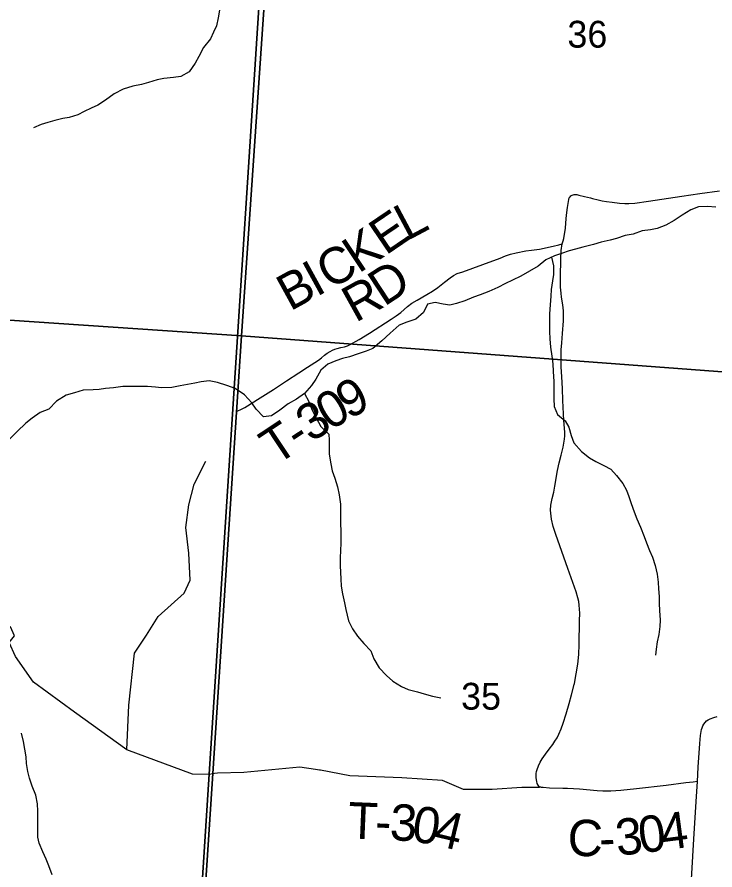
# Model space of a CAD drawing. Extents: x 0 to 34, y 0 to 22.
# Drawn here: x 3.095 to 4.184, y 17.112 to 18.443 of the extents above; entities that cross this region are included whole.
import ezdxf

# ---------------------------------------------------------------- set-up
doc = ezdxf.new("R2010")
doc.units = 0
for name, color, linetype in [('GM_X_Corporation', 7, 'Continuous'), ('GM_X_County_Road', 7, 'Continuous'), ('GM_X_County_Road_Text', 7, 'Continuous'), ('GM_X_Minor_River', 7, 'Continuous'), ('GM_X_Section_Text', 7, 'Continuous'), ('GM_X_Township_Road', 7, 'Continuous'), ('GM_X_Township_Road_Text', 7, 'Continuous'), ('GM_X_Township_Text', 7, 'Continuous')]:
    doc.layers.add(name, color=color, linetype=linetype)

msp = doc.modelspace()

# ---------------------------------------------------------------- linework, layer by layer
at = {"layer": 'GM_X_Corporation'}
for points in [[(2.1, 19.0816), (2.1, 14.1), (3.1902, 14.1), (3.1919, 14.1255), (3.2339, 14.7735), (3.2844, 15.554), (3.3059, 15.8844), (3.3516, 16.5898), (3.3951, 17.2616), (3.507, 18.9883), (2.9513, 19.0267), (2.509, 19.0572), (2.4972, 19.0545), (2.4649, 19.0567)], [(2.5061, 19.0541), (2.5182, 19.0533), (3.5166, 18.9866), (3.4457, 17.9455), (2.436, 18.0137)], [(3.5166, 18.9866), (4.5247, 18.9179), (4.4596, 17.8697), (3.4457, 17.9455)], [(2.436, 18.0137), (3.4457, 17.9455), (3.3779, 16.9127), (2.3682, 16.9741)], [(3.4457, 17.9455), (4.4596, 17.8697), (4.3853, 16.8539), (3.3779, 16.9127)]]:
    msp.add_lwpolyline(points, close=True, dxfattribs=at)
at = {"layer": 'GM_X_County_Road'}
for points in [[(4.1567, 17.2497), (4.1502, 17.249), (4.1386, 17.2477), (4.1078, 17.2439), (4.0617, 17.2384), (4.0371, 17.236), (4.0216, 17.235), (4.0093, 17.2348), (4.0001, 17.2352), (3.9725, 17.2378), (3.9539, 17.2388), (3.9469, 17.2391), (3.9261, 17.2398), (3.9159, 17.2405), (3.9136, 17.2406), (3.9122, 17.2409), (3.9105, 17.2416), (3.9093, 17.2427), (3.9081, 17.2442), (3.9069, 17.2468), (3.9059, 17.2502), (3.9056, 17.2523), (3.905, 17.2563), (3.905, 17.2594), (3.9052, 17.2625), (3.9057, 17.2655), (3.9065, 17.2685), (3.9086, 17.2743), (3.9112, 17.2799), (3.9144, 17.2851), (3.9198, 17.2927), (3.9254, 17.3002), (3.9309, 17.3076), (3.9344, 17.3128), (3.9376, 17.3181), (3.9404, 17.3236), (3.9441, 17.3322), (3.9473, 17.3409), (3.9519, 17.3558), (3.9566, 17.3716), (3.9603, 17.3852), (3.9644, 17.4013), (3.9647, 17.4027), (3.9677, 17.4182), (3.9701, 17.4329), (3.9715, 17.4483), (3.9722, 17.4637), (3.9728, 17.5007), (3.9731, 17.5129), (3.9729, 17.519), (3.9724, 17.525), (3.9714, 17.531), (3.97, 17.5369), (3.9676, 17.546), (3.9547, 17.5825), (3.9356, 17.6354), (3.9318, 17.6481), (3.9291, 17.6596), (3.9279, 17.6686), (3.9277, 17.6733), (3.9282, 17.6814), (3.9302, 17.6915), (3.9325, 17.7017), (3.9344, 17.7109), (3.9385, 17.7355), (3.9411, 17.7475), (3.9442, 17.7595), (3.947, 17.7717), (3.9482, 17.7781), (3.9491, 17.7842), (3.9496, 17.7895), (3.9496, 17.795), (3.9481, 17.8135), (3.9469, 17.8446), (3.9463, 17.8633), (3.9451, 17.8818), (3.9443, 17.8974), (3.9439, 17.9132), (3.9441, 17.9238), (3.9451, 17.9345), (3.9462, 17.9495), (3.9476, 17.9692), (3.9479, 17.9784), (3.9477, 17.9845), (3.9469, 17.9938), (3.9447, 18.006), (3.9439, 18.0121), (3.9433, 18.0215), (3.9431, 18.0371), (3.9435, 18.066), (3.9443, 18.0786), (3.9456, 18.0893), (3.9473, 18.094), (3.9482, 18.0978), (3.9488, 18.1011), (3.9507, 18.1131), (3.9514, 18.1219), (3.9524, 18.1341), (3.9539, 18.1462), (3.9553, 18.1554), (3.956, 18.1586), (3.9568, 18.1608), (3.9579, 18.1628), (3.9591, 18.164), (3.9602, 18.1649), (3.9615, 18.1654), (3.963, 18.1658), (3.9642, 18.166), (3.9661, 18.1661), (3.9686, 18.166), (3.9717, 18.1654), (3.9807, 18.1631), (3.9897, 18.161), (3.9929, 18.1601), (4.0019, 18.158), (4.0083, 18.1566), (4.0148, 18.1555), (4.0236, 18.1545), (4.035, 18.1529), (4.0435, 18.1522), (4.0496, 18.1521), (4.0588, 18.1528), (4.0803, 18.1557), (4.1325, 18.1637), (4.1602, 18.168), (4.191, 18.1718)], [(4.1474, 17.0974), (4.1516, 17.1686), (4.1554, 17.2263), (4.1567, 17.2497), (4.158, 17.2722), (4.1604, 17.3093), (4.1615, 17.3216), (4.1624, 17.3278), (4.1631, 17.3309), (4.1641, 17.3339), (4.1653, 17.3368), (4.1668, 17.3396), (4.1686, 17.3422), (4.1709, 17.3445), (4.1734, 17.3464), (4.1764, 17.3478), (4.1821, 17.3498), (4.1877, 17.3514)]]:
    msp.add_lwpolyline(points, dxfattribs=at)
at = {"layer": 'GM_X_Minor_River'}
for p, q in [((3.4112, 18.454), (3.4093, 18.4422)), ((3.4093, 18.4422), (3.4063, 18.4297)), ((3.4063, 18.4297), (3.4018, 18.4198)), ((3.4018, 18.4198), (3.3969, 18.4092)), ((3.3969, 18.4092), (3.3864, 18.3959)), ((3.3864, 18.3959), (3.3789, 18.3818)), ((3.3789, 18.3818), (3.3732, 18.3712)), ((3.3732, 18.3712), (3.3638, 18.3575)), ((3.3245, 18.3474), (3.3139, 18.3451)), ((3.3393, 18.3487), (3.3245, 18.3474)), ((3.3506, 18.3506), (3.3393, 18.3487)), ((3.3638, 18.3575), (3.3506, 18.3506)), ((3.2761, 18.3355), (3.261, 18.3305)), ((3.2893, 18.3382), (3.2761, 18.3355)), ((3.3003, 18.3413), (3.2893, 18.3382)), ((3.3139, 18.3451), (3.3003, 18.3413)), ((3.2466, 18.3232), (3.2334, 18.3133)), ((3.261, 18.3305), (3.2466, 18.3232)), ((3.2213, 18.3057), (3.2107, 18.3011)), ((3.2334, 18.3133), (3.2213, 18.3057)), ((3.2002, 18.2957), (3.19, 18.2908)), ((3.2107, 18.3011), (3.2002, 18.2957)), ((3.154, 18.2819), (3.1435, 18.2784)), ((3.1665, 18.285), (3.154, 18.2819)), ((3.1764, 18.2865), (3.1665, 18.285)), ((3.19, 18.2908), (3.1764, 18.2865)), ((3.1332, 18.2753), (3.1208, 18.2704)), ((3.1435, 18.2784), (3.1332, 18.2753)), ((3.9292, 18.0683), (3.9322, 18.0549)), ((3.9322, 18.0549), (3.9319, 18.0413)), ((3.9319, 18.0413), (3.9304, 18.0314)), ((3.9304, 18.0314), (3.9286, 18.0178)), ((3.9286, 18.0178), (3.9278, 18.0075)), ((3.9278, 18.0075), (3.9268, 17.9939)), ((3.9268, 17.9939), (3.926, 17.9799)), ((3.926, 17.9799), (3.9257, 17.9655)), ((3.9257, 17.9655), (3.9261, 17.9522)), ((3.9261, 17.9522), (3.9266, 17.9408)), ((3.9266, 17.9408), (3.9277, 17.9279)), ((3.9277, 17.9279), (3.9297, 17.9139)), ((3.9297, 17.9139), (3.9309, 17.9018)), ((3.9309, 17.9018), (3.9317, 17.8897)), ((3.9317, 17.8897), (3.9325, 17.8745)), ((3.9325, 17.8745), (3.9329, 17.8609)), ((3.5438, 17.8557), (3.5507, 17.8433)), ((3.9329, 17.8609), (3.9329, 17.8472)), ((3.5507, 17.8433), (3.5553, 17.8304)), ((3.9329, 17.8472), (3.9334, 17.8351)), ((3.5553, 17.8304), (3.5618, 17.8175)), ((3.9334, 17.8351), (3.9383, 17.823)), ((3.5618, 17.8175), (3.5694, 17.8039)), ((3.9383, 17.823), (3.9501, 17.8132)), ((3.9501, 17.8132), (3.9558, 17.803)), ((3.5694, 17.8039), (3.5815, 17.7922)), ((3.9558, 17.803), (3.9596, 17.7901)), ((3.5815, 17.7922), (3.5823, 17.7828)), ((3.9596, 17.7901), (3.9638, 17.7788)), ((3.5823, 17.7828), (3.582, 17.771)), ((3.9638, 17.7788), (3.976, 17.7652)), ((3.582, 17.771), (3.582, 17.7608)), ((3.582, 17.7608), (3.5847, 17.7456)), ((3.976, 17.7652), (3.9881, 17.755)), ((3.9881, 17.755), (3.998, 17.7494)), ((3.998, 17.7494), (4.0109, 17.7434)), ((3.5847, 17.7456), (3.5867, 17.735)), ((3.5867, 17.735), (3.5909, 17.7233)), ((4.0109, 17.7434), (4.0215, 17.7377)), ((4.0215, 17.7377), (4.0306, 17.7275)), ((3.5909, 17.7233), (3.5951, 17.7097)), ((4.0306, 17.7275), (4.0405, 17.7151)), ((3.5951, 17.7097), (3.5978, 17.6972)), ((4.0405, 17.7151), (4.0462, 17.7049)), ((3.5978, 17.6972), (3.6001, 17.6828)), ((4.0462, 17.7049), (4.0497, 17.695)), ((4.0497, 17.695), (4.0535, 17.6841)), ((3.6001, 17.6828), (3.6001, 17.6718)), ((4.0535, 17.6841), (4.0581, 17.6708)), ((3.6001, 17.6718), (3.6003, 17.6214)), ((4.0581, 17.6708), (4.0623, 17.6602)), ((4.0623, 17.6602), (4.068, 17.647)), ((4.068, 17.647), (4.0737, 17.6326)), ((4.0737, 17.6326), (4.0772, 17.6224)), ((3.6003, 17.6214), (3.6, 17.6112)), ((4.0772, 17.6224), (4.0818, 17.6103)), ((3.6, 17.6112), (3.5996, 17.5986)), ((4.0818, 17.6103), (4.0867, 17.6001)), ((4.0867, 17.6001), (4.0905, 17.5872)), ((3.5996, 17.5986), (3.5993, 17.5873)), ((3.5993, 17.5873), (3.5997, 17.5763)), ((4.0905, 17.5872), (4.0936, 17.5736)), ((3.5997, 17.5763), (3.6005, 17.5661)), ((4.0936, 17.5736), (4.0956, 17.5611)), ((3.6005, 17.5661), (3.6009, 17.5551)), ((4.0956, 17.5611), (4.096, 17.5508)), ((3.6009, 17.5551), (3.6029, 17.5429)), ((4.096, 17.5508), (4.0968, 17.5387)), ((3.6029, 17.5429), (3.6059, 17.5286)), ((4.0968, 17.5387), (4.0968, 17.5277)), ((3.6059, 17.5286), (3.6082, 17.5183)), ((4.0968, 17.5277), (4.0976, 17.5167)), ((3.6082, 17.5183), (3.6125, 17.5005)), ((4.0976, 17.5167), (4.0984, 17.502)), ((3.6125, 17.5005), (3.6186, 17.4881)), ((4.0984, 17.502), (4.0981, 17.4917)), ((3.6186, 17.4881), (3.6262, 17.4767)), ((4.0981, 17.4917), (4.0962, 17.4792)), ((3.6262, 17.4767), (3.6361, 17.4654)), ((4.094, 17.4678), (4.0925, 17.4565)), ((4.0962, 17.4792), (4.094, 17.4678)), ((3.6361, 17.4654), (3.6471, 17.4537)), ((3.6471, 17.4537), (3.652, 17.4412)), ((4.0925, 17.4565), (4.091, 17.447)), ((3.652, 17.4412), (3.66, 17.4272)), ((3.66, 17.4272), (3.6718, 17.4155)), ((3.6718, 17.4155), (3.6813, 17.4065)), ((3.6813, 17.4065), (3.695, 17.3982)), ((3.695, 17.3982), (3.7052, 17.3937)), ((3.7052, 17.3937), (3.72, 17.39)), ((3.72, 17.39), (3.7302, 17.387)), ((3.7302, 17.387), (3.7435, 17.3829)), ((3.7435, 17.3829), (3.7563, 17.3803)), ((3.1052, 17.3126), (3.1021, 17.3254)), ((3.1098, 17.2883), (3.1052, 17.3126)), ((3.1103, 17.2781), (3.1098, 17.2883)), ((3.1122, 17.2656), (3.1103, 17.2781)), ((3.1145, 17.2554), (3.1122, 17.2656)), ((3.1191, 17.2425), (3.1145, 17.2554)), ((3.1248, 17.2285), (3.1191, 17.2425)), ((3.1271, 17.2153), (3.1248, 17.2285)), ((3.1279, 17.2035), (3.1271, 17.2153)), ((3.128, 17.1872), (3.1279, 17.2035)), ((3.1277, 17.1732), (3.128, 17.1872)), ((3.1277, 17.1633), (3.1277, 17.1732)), ((3.13, 17.1535), (3.1277, 17.1633)), ((3.1357, 17.1403), (3.13, 17.1535)), ((3.1407, 17.1289), (3.1357, 17.1403)), ((3.1449, 17.1183), (3.1407, 17.1289)), ((3.1499, 17.1043), (3.1449, 17.1183))]:
    msp.add_line(p, q, dxfattribs=at)
for points in [[(4.1855, 18.1463), (4.1722, 18.1477), (4.1582, 18.1469), (4.1465, 18.1423), (4.1329, 18.1339), (4.1204, 18.1255), (4.1072, 18.1186), (4.094, 18.1133), (4.0834, 18.1113), (4.0705, 18.1094), (4.0566, 18.1044), (4.0441, 18.1021), (4.0305, 18.0974), (4.0206, 18.0951), (4.0066, 18.0917), (3.9945, 18.0882), (3.9779, 18.0839), (3.9662, 18.0809), (3.9564, 18.0785), (3.9446, 18.0743), (3.9337, 18.0705), (3.9204, 18.064), (3.908, 18.0544), (3.8948, 18.0464), (3.8812, 18.0388), (3.8683, 18.0323), (3.857, 18.0273), (3.8453, 18.0212), (3.8313, 18.0147), (3.8177, 18.0097), (3.8071, 18.0062), (3.7939, 18.0005), (3.7807, 17.9959), (3.7704, 17.9936), (3.7602, 17.995), (3.7477, 17.9976), (3.7356, 17.9949), (3.7292, 17.982), (3.7175, 17.9717), (3.7035, 17.9667), (3.6915, 17.9621), (3.6771, 17.9499), (3.6643, 17.9378), (3.6503, 17.9256), (3.6397, 17.9217), (3.6276, 17.9175), (3.614, 17.9129), (3.6031, 17.9102), (3.5925, 17.9064), (3.58, 17.9014), (3.5691, 17.8922), (3.5612, 17.8778), (3.5544, 17.8683), (3.5438, 17.8557), (3.531, 17.847), (3.5182, 17.8393), (3.505, 17.8298), (3.4921, 17.821), (3.4796, 17.8191), (3.4682, 17.8311), (3.4614, 17.841), (3.45, 17.8534), (3.4356, 17.8632), (3.4227, 17.8681), (3.4079, 17.8729), (3.395, 17.8752), (3.3826, 17.8736), (3.3727, 17.872), (3.3614, 17.8697), (3.3497, 17.8674), (3.3368, 17.865), (3.3209, 17.8646), (3.3111, 17.8653), (3.2989, 17.8664), (3.2864, 17.8667)], [(3.2864, 17.8667), (3.2603, 17.8666), (3.246, 17.8646), (3.2335, 17.8634), (3.2236, 17.8619), (3.2138, 17.8611), (3.1987, 17.8606), (3.1847, 17.8568), (3.1718, 17.8529), (3.1571, 17.8438), (3.145, 17.8312), (3.1314, 17.8262), (3.119, 17.8171), (3.1091, 17.8094), (3.0956, 17.7961), (3.0831, 17.7839), (3.0741, 17.7721), (3.0658, 17.7619), (3.0586, 17.7501), (3.0511, 17.7379), (3.0398, 17.7254), (3.0277, 17.7124), (3.0191, 17.7025), (3.007, 17.6907)]]:
    msp.add_lwpolyline(points, dxfattribs=at)
at = {"layer": 'GM_X_Township_Road'}
for points in [[(3.4379, 17.8277), (3.4466, 17.8316), (3.4505, 17.8338), (3.4748, 17.8489), (3.4954, 17.8618), (3.5157, 17.8752), (3.5347, 17.8877), (3.5485, 17.8965), (3.56, 17.9041), (3.5654, 17.9077), (3.5701, 17.9112), (3.5748, 17.9154), (3.5791, 17.9187), (3.5836, 17.9214), (3.5876, 17.9233), (3.5911, 17.9247), (3.5945, 17.9257), (3.6006, 17.9273), (3.6062, 17.9285), (3.6108, 17.93), (3.6138, 17.9317), (3.629, 17.94), (3.6452, 17.9497), (3.679, 17.9715), (3.6867, 17.9768), (3.6939, 17.9823), (3.7043, 17.9914), (3.7114, 17.9965), (3.7194, 18.0014), (3.7343, 18.0103), (3.7435, 18.0153), (3.7518, 18.0212), (3.762, 18.0292), (3.7708, 18.0362), (3.7764, 18.0399), (3.7819, 18.0427), (3.7905, 18.0456), (3.8373, 18.0626), (3.8446, 18.0655), (3.8487, 18.0671), (3.857, 18.0703), (3.865, 18.073), (3.874, 18.0753), (3.8891, 18.0782), (3.8978, 18.0791), (3.9104, 18.081), (3.9314, 18.0857), (3.9403, 18.0877), (3.9456, 18.0893)], [(3.2664, 17.2994), (3.2699, 17.369), (3.2787, 17.4501), (3.2975, 17.4785), (3.3157, 17.5073), (3.356, 17.544), (3.3656, 17.5643), (3.3635, 17.6065), (3.3584, 17.6465), (3.3631, 17.6819), (3.3717, 17.7143), (3.3897, 17.7498)], [(3.2664, 17.2994), (3.185, 17.3582), (3.1212, 17.4051), (3.0929, 17.4449), (3.0828, 17.4667), (3.0914, 17.4772), (3.0852, 17.4913), (3.068, 17.4857), (3.0464, 17.5021), (3.022, 17.5284), (3.0014, 17.5399), (2.9738, 17.5291)], [(3.4033, 17.2623), (3.4003, 17.2619), (3.3953, 17.2611), (3.3688, 17.2613), (3.2664, 17.2994)], [(3.5669, 17.2679), (3.561, 17.2687), (3.5363, 17.2721), (3.4492, 17.2642), (3.4082, 17.2631), (3.4033, 17.2623)], [(3.9122, 17.2409), (3.9105, 17.2405), (3.9092, 17.2405), (3.906, 17.2406), (3.8874, 17.2405), (3.8827, 17.2407), (3.8365, 17.2373), (3.7917, 17.2376), (3.759, 17.2516), (3.6957, 17.2556), (3.6146, 17.259), (3.5689, 17.2676), (3.5669, 17.2679)]]:
    msp.add_lwpolyline(points, dxfattribs=at)
at = {"layer": 'GM_X_Township_Text'}
msp.add_lwpolyline([(8.9, 18.631), (7.8353, 18.6952), (7.8088, 18.6965), (7.389, 18.725), (7.0845, 18.7457), (7.0714, 18.7466), (7.0255, 18.7497), (6.895, 18.7585), (6.4706, 18.7873), (5.6003, 18.8464), (4.4362, 18.9253), (4.421, 18.9263), (4.2931, 18.935), (3.507, 18.9883), (3.3951, 17.2616), (3.3516, 16.5898), (3.3059, 15.8844), (3.2844, 15.554), (3.2339, 14.7735), (3.1919, 14.1255), (3.1902, 14.1)], dxfattribs=at)

# ---------------------------------------------------------------- texts
at = {"layer": 'GM_X_County_Road_Text'}
for s, rotation, p in [('4', 7.5689, (4.103, 17.1423)), ('C', 358.2801, (3.9535, 17.1343)), ('3', 5.7112, (4.0315, 17.134)), ('0', 7.5689, (4.0683, 17.1377)), ('-', 1.9957, (4.0041, 17.1329))]:
    msp.add_text(s, height=0.0568, rotation=rotation, dxfattribs=at).set_placement(p)
at = {"layer": 'GM_X_Section_Text'}
for s, p in [('36', (3.9538, 18.3955)), ('35', (3.788, 17.3621))]:
    msp.add_text(s, height=0.04186, rotation=0, dxfattribs=at).set_placement(p)
at = {"layer": 'GM_X_Township_Road_Text'}
for s, rotation, p in [('L', 28.018, (3.7039, 18.0935)), ('E', 34.2134, (3.6702, 18.0704)), ('K', 33.709, (3.6281, 18.0423)), ('C', 28.7988, (3.5827, 18.0171)), ('B', 28.765, (3.5213, 17.9834)), ('I', 28.765, (3.5622, 18.0059)), ('D', 33.3048, (3.6679, 17.9905)), ('R', 29.0269, (3.6232, 17.9655)), ('9', 28.483, (3.6127, 17.8145)), ('0', 30.6505, (3.5831, 17.7969)), ('3', 32.2293, (3.5538, 17.7785)), ('T', 33.532, (3.4992, 17.7424)), ('-', 33.1986, (3.5345, 17.7658)), ('T', 357.6343, (3.6106, 17.1613)), ('3', 356.9485, (3.6759, 17.1586)), ('0', 351.2378, (3.7091, 17.1569)), ('4', 346.4242, (3.7422, 17.1518)), ('-', 357.4916, (3.6529, 17.1596))]:
    msp.add_text(s, height=0.0568, rotation=rotation, dxfattribs=at).set_placement(p)

doc.saveas('drawing.dxf')
